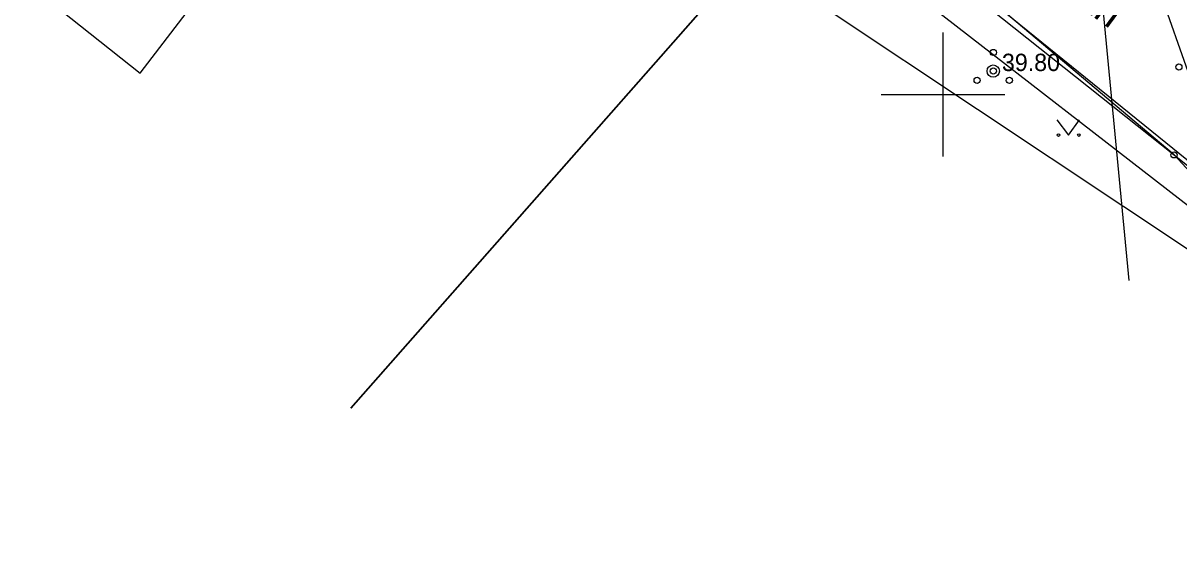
# Model space of a CAD drawing. Extents: x 641898 to 642452, y 6471715 to 6472255.
# Drawn here: x 642312.9 to 642359.52, y 6471781.67 to 6471802.88 of the extents above; entities that cross this region are included whole.
import ezdxf

# ---------------------------------------------------------------- set-up
doc = ezdxf.new("R2010")
doc.units = 0
for name, color, linetype in [('HALJASTUS', 7, 'Continuous'), ('HOONE', 7, 'Continuous'), ('KORGUS-EH2000', 7, 'Continuous'), ('KTRASS', 7, 'Continuous'), ('MPOHULIIN', 7, 'Continuous'), ('PIIR', 7, 'Continuous'), ('PUU', 7, 'Continuous'), ('SIOHULIIN', 7, 'Continuous'), ('TEE', 7, 'Continuous'), ('VORK', 7, 'Continuous'), ('VTRASS', 7, 'Continuous')]:
    doc.layers.add(name, color=color, linetype=linetype)

msp = doc.modelspace()

# ---------------------------------------------------------------- linework, layer by layer
at = {"layer": 'HALJASTUS'}
for p, q in [((642354.594, 6471798.973), (642355.057, 6471798.366)), ((642355.057, 6471798.366), (642355.503, 6471798.973))]:
    msp.add_line(p, q, dxfattribs=at)
for centre in [(642354.656, 6471798.366), (642355.485, 6471798.366)]:
    msp.add_circle(centre, 0.055, dxfattribs=at)
at = {"layer": 'HOONE'}
msp.add_lwpolyline([(642314.435, 6471817.467), (642307.082, 6471823.294), (642300.234, 6471814.661), (642317.624, 6471800.863), (642324.325, 6471809.63), (642317.037, 6471815.406), (642317.205, 6471815.618), (642314.604, 6471817.68), (642314.435, 6471817.467)], dxfattribs=at)
at = {"layer": 'KORGUS-EH2000'}
for centre in [(642352.027, 6471800.947), (642359.515, 6471801.114), (642359.32, 6471797.565)]:
    msp.add_circle(centre, 0.125, dxfattribs=at)
at = {"layer": 'KTRASS'}
msp.add_lwpolyline([(642365.181, 6471793.039), (642325.676, 6471825.028)], dxfattribs=at)
at = {"layer": 'MPOHULIIN'}
for points in [[(642373.322, 6471767.398), (642363.199, 6471791.543), (642355.522, 6471813.313)], [(642357.511, 6471792.498), (642355.522, 6471813.313)]]:
    msp.add_lwpolyline(points, dxfattribs=at)
at = {"layer": 'PIIR'}
for p, q in [((642344.1, 6471807.76), (642326.114, 6471787.348)), ((642370.2, 6471787.49), (642344.1, 6471807.76)), ((642326.114, 6471787.348), (642343.35, 6471806.91))]:
    msp.add_line(p, q, dxfattribs=at)
at = {"layer": 'PUU'}
for centre, radius in [((642352.027, 6471801.697), 0.125), ((642352.027, 6471800.947), 0.25), ((642351.377, 6471800.572), 0.125), ((642352.677, 6471800.572), 0.125)]:
    msp.add_circle(centre, radius, dxfattribs=at)
at = {"layer": 'SIOHULIIN'}
msp.add_lwpolyline([(642382.916, 6471799.858), (642363.199, 6471791.543), (642333.683, 6471811.198), (642353.478, 6471827.095)], dxfattribs=at)
at = {"layer": 'TEE'}
msp.add_lwpolyline([(642366.559, 6471781.691), (642366.75, 6471785.551), (642365.695, 6471788.509), (642364.88, 6471791.554), (642359.32, 6471797.565), (642349.55, 6471805.814), (642345.029, 6471809.364), (642338.375, 6471814.612), (642330.338, 6471821.174), (642323.486, 6471826.682), (642313.328, 6471834.865), (642303.076, 6471843.066), (642293.352, 6471850.788), (642283.707, 6471858.589), (642276.578, 6471864.269), (642271.231, 6471868.612), (642264.701, 6471873.908), (642253.944, 6471882.162), (642243.566, 6471890.342)], dxfattribs=at)
at = {"layer": 'VORK'}
for p, q in [((642350, 6471802.5), (642350, 6471797.5)), ((642347.5, 6471800), (642352.5, 6471800))]:
    msp.add_line(p, q, dxfattribs=at)
at = {"layer": 'VTRASS'}
msp.add_lwpolyline([(642383.722, 6471805.593), (642379.745, 6471805.698), (642375.961, 6471804.651), (642372.001, 6471801.12), (642371.83, 6471800.837), (642365.292, 6471792.802), (642334.532, 6471817.276), (642325.31, 6471824.815), (642293.796, 6471849.944), (642275.212, 6471864.371), (642256.629, 6471878.798), (642256.057, 6471879.253), (642241.436, 6471890.95)], dxfattribs=at)

# ---------------------------------------------------------------- texts
at = {"layer": 'KORGUS-EH2000'}
msp.add_text('39.80', height=0.7, dxfattribs=at).set_placement((642352.377, 6471800.947))
at = {"layer": 'TEE'}
msp.add_text('Kesk tn', height=1.2, rotation=323.6262, dxfattribs=at).set_placement((642352.426, 6471805.808))

doc.saveas('drawing.dxf')
